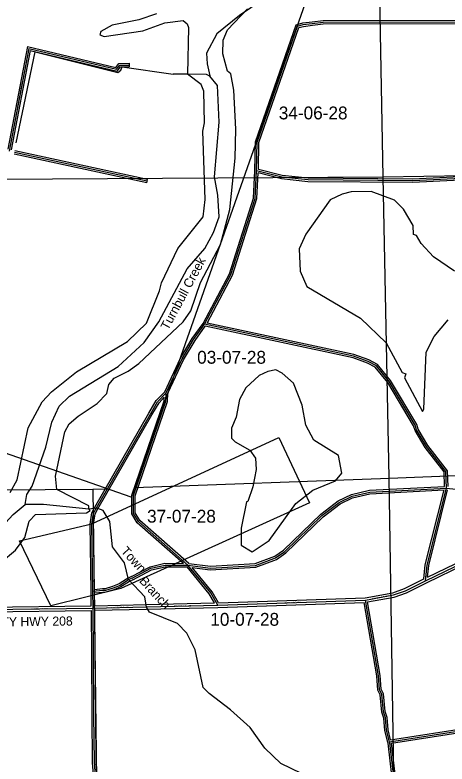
# Model space of a CAD drawing. Extents: x 418523 to 616617, y 1878279 to 2196743.
# Drawn here: x 503197 to 510760, y 2024323 to 2037441 of the extents above; entities that cross this region are included whole.
import ezdxf

# ---------------------------------------------------------------- set-up
doc = ezdxf.new("R2010")
doc.units = 0
for name, color, linetype in [('Level 1', 7, 'Continuous'), ('Level 2', 7, 'Continuous'), ('Level 22', 7, 'Continuous'), ('Level 23', 7, 'Continuous'), ('Level 28', 7, 'Continuous'), ('Level 31', 7, 'Continuous'), ('Level 32', 7, 'Continuous'), ('Level 34', 7, 'Continuous'), ('Level 41', 7, 'Continuous'), ('Level 5', 7, 'Continuous'), ('Level 7', 7, 'Continuous')]:
    doc.layers.add(name, color=color, linetype=linetype)

msp = doc.modelspace()

# ---------------------------------------------------------------- linework, layer by layer
at = {"layer": 'Level 1'}
for p, q in [((513996.157, 2053930.362), (505231.749, 2028993.576)), ((509538.354, 2039979.741), (509638.59, 2034605.156)), ((509638.59, 2034605.156), (520192.044, 2034763.81)), ((497847.24, 2034530.256), (509638.59, 2034605.156)), ((509638.59, 2034605.156), (509743.281, 2029332.589)), ((505231.749, 2028993.576), (497834.481, 2031588.822)), ((504543.388, 2028530.616), (507813.546, 2030039.901)), ((507813.546, 2030039.901), (508352.725, 2028896.927)), ((509755.278, 2029330.532), (515109.977, 2029525.625)), ((505291.082, 2029162.394), (509755.278, 2029330.532)), ((509743.281, 2029332.589), (509820.235, 2024122.176)), ((499119.514, 2029110.237), (504558.071, 2029134.786)), ((504558.071, 2029134.786), (504799.278, 2029143.871)), ((504558.071, 2029134.786), (504621.576, 2024050.486)), ((508352.725, 2028896.927), (505050.598, 2027397.796)), ((503273.486, 2028230.444), (504543.388, 2028530.616)), ((503824.706, 2027095.416), (503273.486, 2028230.444)), ((505050.598, 2027397.796), (503824.706, 2027095.416))]:
    msp.add_line(p, q, dxfattribs=at)
at = {"layer": 'Level 22'}
for p, q in [((510383.934, 2027532.201), (512404.52, 2028513.366)), ((506747.633, 2027103.96), (509332.23, 2027194.206)), ((504563.055, 2027054.055), (505495.32, 2027075.287)), ((505495.32, 2027075.287), (506747.633, 2027103.96))]:
    msp.add_line(p, q, dxfattribs=at)
for points in [[(509332.23, 2027194.206), (509824.34, 2027284.236), (510033.123, 2027358.316), (510383.934, 2027532.201)], [(500500.163, 2026185.621), (501142.785, 2026416.726), (501969.911, 2026897.268), (502270.317, 2026979.281), (502687.499, 2027027.71), (504563.055, 2027054.055)]]:
    msp.add_lwpolyline(points, dxfattribs=at)
at = {"layer": 'Level 23'}
for p, q in [((510401.407, 2027496.218), (512395.237, 2028464.391)), ((510419.883, 2027594.125), (512387.048, 2028549.349)), ((505494.405, 2027115.277), (506690.929, 2027142.672)), ((506748.55, 2027063.969), (509308.817, 2027153.361)), ((506759.074, 2027144.383), (509327.91, 2027234.079)), ((504592.556, 2027094.737), (505494.41, 2027115.277)), ((504593.392, 2027014.733), (505496.231, 2027035.296)), ((505496.236, 2027035.296), (506748.55, 2027063.969))]:
    msp.add_line(p, q, dxfattribs=at)
for points in [[(509327.91, 2027234.079), (509813.987, 2027323.007), (510017.497, 2027395.216), (510356.728, 2027563.361)], [(509368.527, 2027160.18), (509834.694, 2027245.466), (510048.75, 2027321.416), (510401.407, 2027496.218)], [(500513.182, 2026147.792), (501159.74, 2026380.315), (501985.487, 2026860.056), (502277.935, 2026939.896), (502690.093, 2026987.741), (504533.397, 2027013.632)], [(500527.937, 2026238.118), (501125.831, 2026453.138), (501954.335, 2026934.481), (502262.7, 2027018.666), (502684.905, 2027067.678), (504532.564, 2027093.631)]]:
    msp.add_lwpolyline(points, dxfattribs=at)
at = {"layer": 'Level 31'}
for p, q in [((507436.851, 2035212.816), (508144.856, 2037244.311)), ((503436.763, 2036854.241), (503092.809, 2035054.052)), ((507426.579, 2034712.81), (507436.851, 2035212.816)), ((505508.32, 2034528.304), (503190.289, 2035032.913)), ((507868.045, 2034602.638), (507426.579, 2034712.81)), ((504559.497, 2027342.096), (504543.795, 2028521.182)), ((505248.662, 2027576.716), (505190.26, 2027551.865)), ((504563.055, 2027054.055), (504559.497, 2027342.096)), ((504569.864, 2026251.042), (504563.055, 2027054.055)), ((504579.355, 2025178.176), (504569.864, 2026251.042))]:
    msp.add_line(p, q, dxfattribs=at)
for points in [[(508144.856, 2037244.311), (508242.527, 2037271.19), (508400.67, 2037290.551), (508591.45, 2037312.689), (511865.525, 2037320.31), (512146.616, 2037271.194), (514024.296, 2037332.194), (514141.449, 2037319.736), (514319.586, 2037268.492), (514512.657, 2037228.829), (514691.284, 2037221.953), (514828.721, 2037212.328), (515649.405, 2037282.98), (515889.65, 2037319.513), (516496.51, 2037388.826), (516684.196, 2037431.748), (516809.834, 2037401.446), (516900.235, 2037350.914), (516944.05, 2037294.741), (517252.19, 2036777.156)], [(503436.763, 2036854.241), (504973.153, 2036489.255), (505031.745, 2036563.565), (505195.517, 2036563.977)], [(506515.89, 2032023.552), (506977.88, 2032897.016), (507399.582, 2034229.237), (507426.579, 2034712.81)], [(512211.3, 2034636.146), (510160.352, 2034535.563), (508326.225, 2034550.955), (507868.045, 2034602.638)], [(510748.434, 2029156.351), (511131.63, 2029113.367), (511273.7, 2029145.896), (511549.929, 2029453.556), (511650.32, 2029602.991), (511743.287, 2029877.92), (511766.167, 2031578.349), (511801.44, 2032086.62), (511852.748, 2032403.537)], [(505844.712, 2030825.471), (506121.821, 2031416.386), (506323.13, 2031757.41), (506515.89, 2032023.552)], [(510748.434, 2029156.351), (510741.04, 2029448.043), (510400.916, 2029882.895), (510227.196, 2030175.253), (510202.501, 2030258.996), (509746.789, 2031019.074), (509522.64, 2031295.273), (509381.328, 2031370.757), (509123.181, 2031463.441), (506515.89, 2032023.552)], [(504622.92, 2028806.335), (505568.17, 2030451.304), (505693.89, 2030667.896), (505844.712, 2030825.471)], [(506224.859, 2027806.168), (505360.8, 2028568.346), (505269.82, 2028710.191), (505270.811, 2029026.943), (505835.541, 2030675.676), (505844.712, 2030825.471)], [(506224.859, 2027806.168), (506616.585, 2027754.738), (507408.572, 2027801.688), (507759.223, 2027933.726), (507918.083, 2028041.818), (508570.791, 2028672.685), (508871.772, 2028904.945), (509097.157, 2029012.41), (509406.05, 2029086.446), (510748.434, 2029156.351)], [(510383.934, 2027532.201), (510409.745, 2027807.033), (510748.434, 2029156.351)], [(504543.795, 2028521.182), (504569.305, 2028713.094), (504622.92, 2028806.335)], [(505248.662, 2027576.716), (505574.463, 2027750.296), (505824.691, 2027807.816), (506224.859, 2027806.168)], [(506747.633, 2027103.96), (506623.366, 2027321.216), (506224.859, 2027806.168)], [(505190.26, 2027551.865), (505164.525, 2027534.879), (505035.22, 2027450.679), (504914.932, 2027401.718), (504779.789, 2027361.547), (504732.883, 2027358.833), (504559.497, 2027342.096)], [(509750.674, 2024713.754), (509698.57, 2024916.89), (509682.645, 2025133.701), (509649.778, 2025234.206), (509617.743, 2025542.726), (509576.251, 2025626.172), (509560.428, 2025868.076), (509332.23, 2027194.206)], [(509750.674, 2024713.754), (511206.949, 2024937.053), (512520.692, 2025180.609), (512588.321, 2025215.256), (512714.857, 2025323.131), (513146.03, 2025869.488), (513275.695, 2025968.262), (513745.476, 2026587.573), (513822.214, 2026684.01), (513948.615, 2026759.523), (514048.513, 2026782.409), (514104.051, 2026805.467), (514139.675, 2026840.241), (514204.824, 2026971.999), (514221.233, 2027036.305)], [(504610.109, 2024036.124), (504586.39, 2024352.979), (504579.355, 2025178.176)], [(509828.984, 2024091.202), (509756.29, 2024691.911), (509750.674, 2024713.754)]]:
    msp.add_lwpolyline(points, dxfattribs=at)
at = {"layer": 'Level 32'}
for p, q in [((507406.955, 2035218.193), (508121.711, 2037269.058)), ((507466.749, 2035207.438), (508168.003, 2037219.564)), ((503413.182, 2036890.676), (503069.377, 2035091.271)), ((503460.345, 2036817.801), (503127.77, 2035077.168)), ((505195.441, 2036593.978), (505195.592, 2036533.976)), ((507396.596, 2034713.955), (507406.955, 2035218.193)), ((507457.066, 2034736.121), (507466.749, 2035207.438)), ((505514.701, 2034557.618), (503196.67, 2035062.227)), ((505501.94, 2034498.989), (503183.908, 2035003.598)), ((507862.709, 2034573.048), (507454.512, 2034674.917)), ((507873.383, 2034632.226), (507457.066, 2034736.121)), ((505501.94, 2034498.989), (505514.701, 2034557.618)), ((504529.5, 2027341.697), (504513.77, 2028522.968)), ((504589.061, 2027375.09), (504573.823, 2028519.395)), ((505235.711, 2027603.808), (505176.007, 2027578.403)), ((505261.615, 2027549.623), (505204.514, 2027525.326)), ((504532.564, 2027093.631), (504529.499, 2027341.726)), ((504592.557, 2027094.738), (504589.837, 2027314.885)), ((504539.865, 2026250.788), (504533.397, 2027013.632)), ((504599.863, 2026251.296), (504593.391, 2027014.733)), ((504549.355, 2025177.91), (504539.865, 2026250.777)), ((504609.355, 2025178.44), (504599.863, 2026251.307)), ((509858.907, 2024093.661), (509786.868, 2024688.951))]:
    msp.add_line(p, q, dxfattribs=at)
for points in [[(508121.711, 2037269.056), (508236.694, 2037300.701), (508397.118, 2037320.341), (508589.681, 2037342.686), (511868.091, 2037350.316), (512148.733, 2037301.279), (514025.4, 2037362.246), (514147.225, 2037349.292), (514326.763, 2037297.646), (514516.276, 2037258.712), (514692.909, 2037251.913), (514828.48, 2037242.419), (515645.86, 2037312.786), (515885.691, 2037349.256), (516491.448, 2037418.444), (516684.379, 2037462.565), (516820.875, 2037429.645), (516920.163, 2037374.144), (516968.865, 2037311.707), (517273.588, 2036799.86)], [(508168.003, 2037219.565), (508248.361, 2037241.679), (508404.222, 2037260.761), (508593.22, 2037282.692), (511862.959, 2037290.303), (512144.499, 2037241.109), (514023.191, 2037302.141), (514135.673, 2037290.181), (514312.41, 2037239.339), (514509.037, 2037198.946), (514689.658, 2037191.992), (514828.962, 2037182.237), (515652.95, 2037253.173), (515893.609, 2037289.769), (516501.573, 2037359.209), (516684.015, 2037400.931), (516798.794, 2037373.248), (516880.306, 2037327.684), (516919.235, 2037277.776), (517196.25, 2036812.47)], [(503413.183, 2036890.677), (504961.453, 2036522.87), (505017.167, 2036593.528), (505195.441, 2036593.978)], [(503460.345, 2036817.801), (504984.853, 2036455.64), (505046.324, 2036533.601), (505195.592, 2036533.976)], [(506490.357, 2032039.443), (506950.095, 2032908.649), (507369.84, 2034234.686), (507396.596, 2034713.954)], [(506560.941, 2032044.559), (507005.665, 2032885.381), (507429.325, 2034223.79), (507454.511, 2034674.917)], [(512165.318, 2034663.926), (510159.742, 2034565.57), (508328.036, 2034580.941), (507873.382, 2034632.226)], [(512180.268, 2034604.586), (510160.961, 2034505.556), (508324.412, 2034520.968), (507862.71, 2034573.048)], [(505819.64, 2030842.661), (506095.263, 2031430.412), (506298.009, 2031773.87), (506490.357, 2032039.443)], [(505874.307, 2030817.919), (506148.38, 2031402.361), (506348.25, 2031740.95), (506528.715, 2031990.112)], [(510717.704, 2029184.791), (510711.3, 2029437.371), (510376.104, 2029865.922), (510199.484, 2030163.161), (510174.807, 2030246.846), (509722.152, 2031001.821), (509503.163, 2031271.665), (509369.126, 2031343.262), (509114.925, 2031434.53), (506528.715, 2031990.112)], [(510777.764, 2029183.249), (510770.78, 2029458.716), (510425.728, 2029899.868), (510254.908, 2030187.345), (510230.196, 2030271.145), (509771.425, 2031036.326), (509542.118, 2031318.881), (509393.53, 2031398.252), (509131.437, 2031492.353), (506560.941, 2032044.559)], [(504596.908, 2028821.283), (505542.191, 2030466.308), (505669.741, 2030686.054), (505819.639, 2030842.661)], [(506237.84, 2027834.721), (505383.79, 2028588.072), (505299.848, 2028718.941), (505300.796, 2029021.901), (505865.238, 2030669.794), (505874.307, 2030817.919)], [(504648.931, 2028791.387), (505594.15, 2030436.3), (505718.04, 2030649.739), (505809.765, 2030745.57)], [(506145.125, 2027836.496), (505337.811, 2028548.621), (505239.792, 2028701.439), (505240.826, 2029031.985), (505805.845, 2030681.56), (505809.765, 2030745.569)], [(506237.84, 2027834.721), (506617.66, 2027784.856), (507402.257, 2027831.366), (507745.303, 2027960.542), (507899.081, 2028065.176), (508551.141, 2028695.416), (508855.975, 2028930.65), (509087.095, 2029040.848), (509401.738, 2029116.262), (510717.704, 2029184.791)], [(506296.258, 2027766.536), (506615.511, 2027724.621), (507414.888, 2027772.009), (507773.143, 2027906.911), (507937.085, 2028018.46), (508590.441, 2028649.954), (508887.57, 2028879.241), (509107.22, 2028983.971), (509410.363, 2029056.629), (510709.453, 2029124.278)], [(510356.728, 2027563.361), (510380.09, 2027812.116), (510709.454, 2029124.278)], [(510419.883, 2027594.125), (510439.4, 2027801.949), (510771.15, 2029123.612)], [(504513.769, 2028522.968), (504540.346, 2028722.916), (504596.912, 2028821.291)], [(504573.824, 2028519.395), (504598.265, 2028703.271), (504648.927, 2028791.38)], [(505235.711, 2027603.808), (505563.866, 2027778.643), (505821.348, 2027837.831), (506145.125, 2027836.496)], [(505261.615, 2027549.622), (505585.06, 2027721.949), (505828.034, 2027777.801), (506210.634, 2027776.225)], [(506690.93, 2027142.671), (506598.581, 2027304.125), (506210.634, 2027776.225)], [(506759.074, 2027144.383), (506648.152, 2027338.307), (506296.258, 2027766.536)], [(505176.007, 2027578.403), (505148.076, 2027559.969), (505021.253, 2027477.385), (504904.979, 2027430.058), (504774.579, 2027391.297), (504730.575, 2027388.751), (504589.062, 2027375.09)], [(505204.514, 2027525.326), (505180.975, 2027509.79), (505049.188, 2027423.974), (504924.885, 2027373.378), (504784.998, 2027331.797), (504735.192, 2027328.916), (504589.837, 2027314.884)], [(509721.614, 2024706.3), (509668.847, 2024912.026), (509652.993, 2025127.854), (509620.268, 2025227.923), (509588.464, 2025534.229), (509546.708, 2025618.206), (509530.594, 2025864.543), (509308.817, 2027153.361)], [(509772.985, 2024747.525), (509728.295, 2024921.754), (509712.297, 2025139.548), (509679.287, 2025240.487), (509647.023, 2025551.223), (509605.795, 2025634.138), (509590.262, 2025871.609), (509368.527, 2027160.18)], [(509772.985, 2024747.526), (511201.94, 2024966.636), (512510.915, 2025209.308), (512571.524, 2025240.359), (512693.14, 2025344.041), (513124.831, 2025891.054), (513254.264, 2025989.65), (513721.785, 2026605.981), (513802.139, 2026706.963), (513937.297, 2026787.708), (514039.346, 2026811.086), (514087.221, 2026830.963), (514115.052, 2026858.131), (514176.534, 2026982.471), (514192.164, 2027043.723)], [(509786.868, 2024688.951), (511211.957, 2024907.47), (512530.47, 2025151.911), (512605.119, 2025190.153), (512736.574, 2025302.222), (513167.23, 2025847.923), (513297.127, 2025946.875), (513769.168, 2026569.164), (513842.289, 2026661.056), (513959.934, 2026731.339), (514057.68, 2026753.731), (514120.881, 2026779.971), (514164.297, 2026822.351), (514233.114, 2026961.526), (514250.302, 2027028.887)], [(504577.809, 2024065.741), (504556.398, 2024351.731), (504549.355, 2025177.92)], [(504637.881, 2024067.027), (504616.381, 2024354.228), (504609.355, 2025178.431)], [(509795.087, 2024121.594), (509726.744, 2024686.35), (509721.618, 2024706.283)]]:
    msp.add_lwpolyline(points, dxfattribs=at)
at = {"layer": 'Level 5'}
msp.add_line((506214.461, 2036401.592), (505964.365, 2036402.38), dxfattribs=at)
for points in [[(507542.406, 2037719.172), (507124.695, 2037431.396), (506730.283, 2037111.161), (506552.149, 2036774.405), (506562.783, 2036586.706), (506607.53, 2036374.866)], [(503217.822, 2035202.499), (503548.063, 2036793.701), (504997.443, 2036430.529), (505047.593, 2036472.041), (505072.803, 2036530.332), (505964.365, 2036402.38)], [(503372.415, 2028866.305), (503406.312, 2029041.269), (503498.502, 2029191.034), (503734.145, 2029873.864), (503843.891, 2030306.996), (503969.849, 2030590.034), (504153.83, 2030764.481), (505005.841, 2031286.923), (505457.345, 2031702.298), (505716.945, 2032068.251), (506211.79, 2032991.989), (506521.381, 2033349.471), (506672.35, 2033632.41), (506773.268, 2033907.187), (506749.46, 2034282.386), (506692.184, 2034607.704), (506770.319, 2035566.158), (506739.027, 2036208.153), (506606.171, 2036366.966), (506547.91, 2036400.516), (506214.461, 2036401.592)], [(500092.309, 2027668.157), (500200.253, 2027534.415), (500449.991, 2027416.895), (500917.021, 2027482.082), (501200.388, 2027456.155), (501300.49, 2027480.836), (502694.95, 2028184.91), (503163.413, 2028691.928), (503372.415, 2028866.305)], [(504489.222, 2028787.676), (503697.532, 2028865.258), (503372.415, 2028866.305)], [(508575.2, 2023980.996), (507851.088, 2024333.476), (507568.526, 2024601.149), (507311.244, 2024960.465), (506970.47, 2025269.988), (506596.247, 2025554.671), (506488.233, 2025663.372), (506348.638, 2026322.406), (506207.86, 2026614.632), (506041.663, 2026781.915), (505550.468, 2026983.554), (505500.715, 2027067.085), (505467.951, 2027250.619), (505185.5, 2027551.643), (505111.413, 2027843.64), (504903.923, 2028127.764), (504855.335, 2028569.725), (504739.249, 2028761.858), (504631.005, 2028803.898), (504489.222, 2028787.676)]]:
    msp.add_lwpolyline(points, dxfattribs=at)
at = {"layer": 'Level 7'}
for points in [[(504489.222, 2028787.676), (504489.421, 2028846.037), (503931.803, 2029131.267), (503907.539, 2029364.753), (504068.449, 2030139.544), (504143.929, 2030280.998), (504302.74, 2030413.893), (504636.914, 2030637.893), (504804.235, 2030812.399), (504838.063, 2030970.693), (504930.123, 2031078.777), (505180.607, 2031203.003), (505364.469, 2031335.798), (506142.095, 2032066.876), (506276.095, 2032258.191), (506444.46, 2032757.816), (506796.706, 2033423.576), (506957.09, 2034031.643), (507051.696, 2034931.676), (507061.668, 2035440.158), (507030.535, 2036123.845), (506973.1, 2036407.471), (506914.907, 2036457.651), (506832.49, 2036758.058), (506841.606, 2036999.784), (506917.255, 2037182.92), (507268.556, 2037548.612)], [(505676.02, 2037462.042), (505367.215, 2037354.686), (504900.086, 2037264.488), (504699.654, 2037148.433), (504682.784, 2037090.111), (504757.716, 2037064.872), (505433.29, 2037162.722), (505817.217, 2037303.19), (506142.464, 2037343.825), (506208.996, 2037285.244), (506233.778, 2037218.492), (506214.461, 2036401.592)], [(503114.645, 2029075.566), (503232.104, 2029300.254), (503426.773, 2030208.298), (503670, 2030666.012), (503837.281, 2030840.549), (504271.915, 2031189.272), (505165.638, 2031719.886), (505500.13, 2032043.927), (505727.045, 2032610.084), (505760.844, 2032751.697), (506046.21, 2033351.006), (506489.831, 2033908.104), (506524.156, 2034208.112), (506486.355, 2035408.681), (506511.823, 2035550.305), (506505.284, 2036108.868), (506455.66, 2036225.741), (506214.461, 2036401.592)], [(510888.39, 2032951.831), (510522.407, 2033203.133), (510306.408, 2033437.236), (510223.504, 2033579.219), (510173.522, 2033596.059), (510165.71, 2033754.482), (509999.89, 2034038.468), (509842.025, 2034197.35), (509434.032, 2034348.749), (509083.874, 2034341.525), (508925.351, 2034300.361), (508716.618, 2034201.017), (508289.498, 2033602.167), (508171.98, 2033344.1), (508187.377, 2032952.261), (508303.235, 2032685.106), (509243.446, 2032131.862), (509692.214, 2031696.937), (509973.98, 2031179.167), (510040.611, 2031153.928), (510015.372, 2031087.296), (510330.22, 2030494.405), (510330.22, 2030494.405), (510355.4, 2030536.026), (510391.973, 2031536.251), (510534.571, 2031810.9), (510777.272, 2032101.88)], [(502952.332, 2027858.975), (503203.105, 2028066.573), (503370.555, 2028291.091), (503446.491, 2028574.298), (503555.222, 2028690.652), (504447.352, 2028721.123), (504514.173, 2028762.576), (504489.222, 2028787.676)]]:
    msp.add_lwpolyline(points, dxfattribs=at)
msp.add_lwpolyline([(507346.212, 2028036.491), (507646.945, 2028235.579), (508115.895, 2028884.31), (508408.418, 2029116.779), (508809.095, 2029282.198), (508917.885, 2029415.252), (508860.549, 2029723.869), (508427.904, 2029992.031), (508287.065, 2030259.256), (508221.488, 2030609.613), (508072.668, 2030993.571), (507873.19, 2031169.263), (507764.977, 2031227.973), (507623.164, 2031195.091), (507472.912, 2031128.887), (507238.77, 2030912.89), (507129.751, 2030704.843), (507070.385, 2030396.595), (506986.396, 2030205.119), (506985.84, 2030030.055), (507052.302, 2029963.134), (507310.28, 2029820.604), (507409.855, 2029678.551), (507417.539, 2029478.446), (507358.233, 2029178.538), (507274.025, 2028920.371), (507248.985, 2028912.131), (507155.81, 2028453.928), (507154.835, 2028153.821), (507346.212, 2028036.491)], close=True, dxfattribs=at)

# ---------------------------------------------------------------- texts
at = {"layer": 'Level 2'}
for s, p in [('34-06-28', (507814.614, 2035612.502)), ('03-07-28', (506385.799, 2031333.254)), ('37-07-28', (505508.687, 2028549.738)), ('10-07-28', (506615.656, 2026743.981))]:
    msp.add_text(s, height=225, dxfattribs=at).set_placement(p)
at = {"layer": 'Level 28'}
msp.add_text('COUNTY HWY 208', height=160, rotation=0.8040805, dxfattribs=at).set_placement((502330.253, 2026722.247))
at = {"layer": 'Level 34'}
for s, height, rotation, p in [('TRUMAN PACETTI ROAD', 25, 79.2985167, (503255.695, 2035828.707)), ('COUNTY HWY 208', 25, 10.3669222, (509439.255, 2027201.081)), ('COUNTY HWY 208', 24.99916, 1.9991027, (507896.844, 2027131.582)), ('COUNTY HWY 208', 25, 0.8040805, (503481.844, 2027026.369)), ('COUNTY HWY 208', 25, 1.3040083, (504885.887, 2027048.907)), ('COUNTY HWY 208', 25, 1.3109139, (505978.177, 2027073.841))]:
    msp.add_text(s, height=height, rotation=rotation, dxfattribs=at).set_placement(p)
at = {"layer": 'Level 41'}
for s, rotation, p in [('Turnbull Creek', 61.7846, (505878.063, 2031908.556)), ('Town', 312.3057001, (505040.115, 2028042.213)), ('Branch', 312.3057001, (505362.371, 2027520.542))]:
    msp.add_text(s, height=160, rotation=rotation, dxfattribs=at).set_placement(p)

doc.saveas('drawing.dxf')
